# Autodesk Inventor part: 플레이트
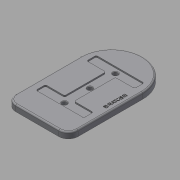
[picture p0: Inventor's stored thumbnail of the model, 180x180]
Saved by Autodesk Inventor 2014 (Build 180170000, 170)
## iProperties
Created: 2016-08
Part Number: 플레이트
Material: 일반
Document SubType Name: Modeling
Designer: mduedu
Density: 1 g/cm^3
Appearance: 기본값
Mass: 325.285 g
Surface Area: 629.196 cm^2
Volume: 325.285 cm^3
Author: mduedu
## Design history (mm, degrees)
sketch "스케치1" dims "d0" = 220, "d2" = 130
  geometry: L1 (110, 65)-(-45, 65); L2 (-45, 65)-(-45, -65); L3 (-45, -65)-(110, -65); L4 (45, -65)-(45, 65); L5 (45, 65)-(-45, -65); L6 (-45, 65)-(45, -65); L7 (110, -65)-(110, 65); 5 further points
  constraints: 14 end point, 5 midpoint, 3 parallel, 2 point on line, 2 vertical alignment, 1 coincident, 1 horizontal, 1 perpendicular, 1 vertical, 4 other
extrude "돌출1" new body sketch "스케치1" distance "d3" = 13; taper "d4" = 0 deg
sketch "스케치2"
  geometry: L1 (-63, -50)-(63, -50); L2 (63, -50)-(63, 50); L3 (63, 50)-(-63, 50); L4 (-63, 50)-(-63, -50); L5 (-63, -50)-(63, 50); L6 (63, -50)-(-63, 50); L7 (-63, 50)-(-43, 50); L8 (-43, 50)-(-43, -50); L9 (-43, -50)-(-63, -50); L10 (-63, -50)-(-63, 50); L11 (63, 50)-(43, 50); L12 (43, 50)-(43, -50); L13 (43, -50)-(63, -50); L14 (63, -50)-(63, 50); L15 (-43, -10)-(43, -10); L16 (43, -10)-(43, 10); L17 (43, 10)-(-43, 10); L18 (-43, 10)-(-43, -10); L19 (-43, -10)-(43, 10); L20 (43, -10)-(-43, 10); 1 further point
  constraints: 40 end point, 8 parallel, 4 horizontal, 4 midpoint, 4 perpendicular, 3 point on line
  dimensions: "d18" = 126 distance of L3.end L2.end; "d19" = 100 distance of L2.end L1.end; "d20" = 20 distance of L8.end L9.end; "d21" = 20 distance of L12.end L13.end (= d20); "d22" = 20 distance of L15.end L16.end
extrude "돌출3" cut sketch "스케치2" distance "d23" = 3; taper "d24" = 0 deg
fillet "모깎기6" dims "d25" = 3
sketch "스케치4"
  geometry: L1 (-40, -10)-(40, -10) reference; L2 (43, -13)-(43, -47) reference; L3 (40, 10)-(-40, 10) reference; L4 (-43, 13)-(-43, 47) reference; L5 (45, -65)-(-110, -65) reference; L6 (-110, 65)-(45, 65) reference; L7 (-53, 40)-(-53, -40); L8 (53, 40)-(53, -40); L9 (-53, 0)-(53, 0); L10 (-46, 50)-(-60, 50) reference; L11 (-63, 47)-(-63, -47) reference; L12 (-60, -50)-(-46, -50) reference; L13 (-43, -47)-(-43, -13) reference; L14 (46, -50)-(60, -50) reference; L15 (63, -47)-(63, 47) reference; L16 (60, 50)-(46, 50) reference; L17 (43, 47)-(43, 13) reference; L18 (-110, -65)-(-110, 65) reference; C1 r 5 at (-53, 0); C2 r 5 at (0, 0); C3 r 5 at (53, 0); A1 r 3 centre (-40, -13) between (-40, -10) and (-43, -13) reference; A2 r 3 centre (40, -13) between (43, -13) and (40, -10) reference; A3 r 3 centre (40, 13) between (40, 10) and (43, 13) reference; A4 r 3 centre (-40, 13) between (-43, 13) and (-40, 10) reference; A5 r 65 centre (45, 0) between (45, -65) and (45, 65) reference; A6 r 3 centre (-46, 47) between (-43, 47) and (-46, 50) reference; A7 r 3 centre (-60, 47) between (-60, 50) and (-63, 47) reference; A8 r 3 centre (-60, -47) between (-63, -47) and (-60, -50) reference; A9 r 3 centre (-46, -47) between (-46, -50) and (-43, -47) reference; A10 r 3 centre (46, -47) between (43, -47) and (46, -50) reference; A11 r 3 centre (60, -47) between (60, -50) and (63, -47) reference; A12 r 3 centre (60, 47) between (63, 47) and (60, 50) reference; A13 r 3 centre (46, 47) between (46, 50) and (43, 47) reference; 1 further point
  constraints: 6 end point, 3 centre point, 3 coincident, 2 midpoint, 1 parallel, 1 perpendicular
  dimensions: "d26" = 10 diameter of C1; "d27" = 10 diameter of C2; "d28" = 10 diameter of C3
extrude "돌출4" cut sketch "스케치4" stored distance "d29" = 3; taper "d30" = 0 deg
chamfer "모따기2" distance "d31" = 1; stored, may be unused: second distance "d32" = 2, angle "d33" = 45 deg
fillet "모깎기7" dims "d34" = 20
fillet "모깎기1" dims "d14" = 3
sketch "스케치3"
  geometry: L1 (-90, -65)-(45, -65) reference; 3 further points
  constraints: 1 vertical alignment, 1 other
  dimensions: "d15" = 12 distance from line of point (0, -53) L1
feature "엠보싱1" sketch "스케치3" dims "d16" = 0.5, "d17" = 0
node "솔리드1"
node "절단 모서리 투영1"
